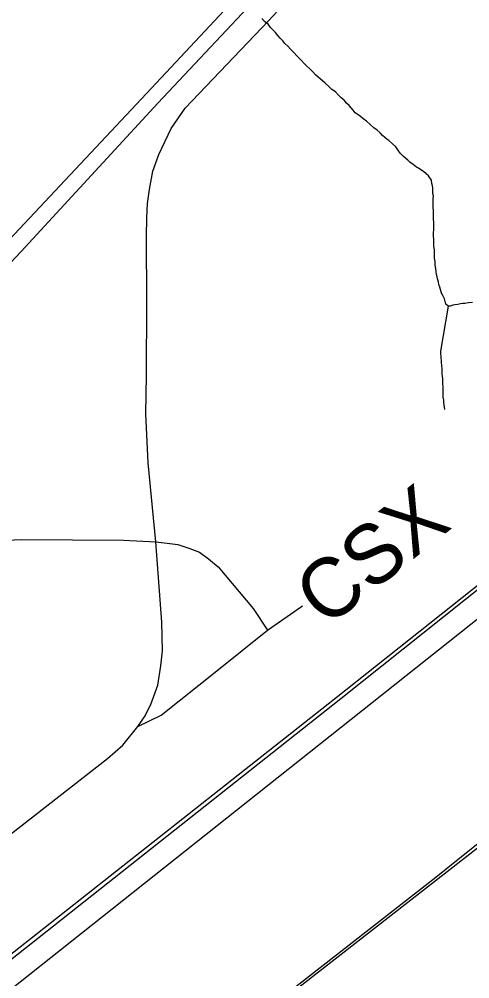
# Model space of a CAD drawing. Extents: x 0 to 34, y 0 to 22.
# Drawn here: x 7.775 to 8.206, y 15.889 to 16.806 of the extents above; entities that cross this region are included whole.
import ezdxf

# ---------------------------------------------------------------- set-up
doc = ezdxf.new("R2010")
doc.units = 0
for name, color, linetype in [('GM_X_City_Street', 7, 'Continuous'), ('GM_X_County_Road', 7, 'Continuous'), ('GM_X_Minor_River', 7, 'Continuous'), ('GM_X_Rail_Line', 7, 'Continuous'), ('GM_X_Rail_Line_Text', 7, 'Continuous'), ('GM_X_State_Route', 7, 'Continuous'), ('GM_X_US_Route', 7, 'Continuous')]:
    doc.layers.add(name, color=color, linetype=linetype)

msp = doc.modelspace()

# ---------------------------------------------------------------- linework, layer by layer
at = {"layer": 'GM_X_City_Street'}
for points in [[(7.65164, 16.30285), (7.77765, 16.30863), (7.87506, 16.30794), (7.90594, 16.30639), (7.91957, 16.30501), (7.92699, 16.3038), (7.93752, 16.30052), (7.94787, 16.29672), (7.95633, 16.29034), (7.96562, 16.28259), (7.99913, 16.24266), (8.01268, 16.22197)], [(7.9643, 16.18343), (8.01268, 16.22197), (8.04612, 16.24543)], [(7.88899, 16.12998), (7.91109, 16.14103), (7.9643, 16.18343)]]:
    msp.add_lwpolyline(points, dxfattribs=at)
at = {"layer": 'GM_X_County_Road'}
msp.add_lwpolyline([(7.73034, 15.99882), (7.85976, 16.09967), (7.87438, 16.11215), (7.88899, 16.12998), (7.89576, 16.14032), (7.90147, 16.15209), (7.90788, 16.16956), (7.91073, 16.1881), (7.91252, 16.20236), (7.9118, 16.22982), (7.90594, 16.30639), (7.89873, 16.38177), (7.89663, 16.4286), (7.89705, 16.46529), (7.89747, 16.53532), (7.89705, 16.59817), (7.89754, 16.61595), (7.89819, 16.62939), (7.89992, 16.64304), (7.90324, 16.66038), (7.90884, 16.67631), (7.92059, 16.70115), (7.9342, 16.72055), (8.01372, 16.80397), (8.59955, 17.43284)], dxfattribs=at)
at = {"layer": 'GM_X_Minor_River'}
for points in [[(8.17186, 16.6046), (8.17179, 16.60726), (8.17174, 16.60917), (8.17168, 16.61145), (8.17159, 16.61488), (8.17153, 16.61716), (8.17148, 16.61944), (8.17143, 16.62134), (8.17138, 16.62325), (8.17132, 16.62553), (8.17126, 16.62782), (8.1712, 16.6301), (8.17115, 16.632), (8.17111, 16.63391), (8.17141, 16.63696), (8.17097, 16.63923), (8.17092, 16.64114), (8.17083, 16.64456), (8.1704, 16.64646), (8.16996, 16.64873), (8.16951, 16.65177), (8.16673, 16.65588), (8.1644, 16.65773), (8.16206, 16.65995), (8.15935, 16.66179), (8.15702, 16.66325), (8.15509, 16.66435), (8.15197, 16.66693), (8.14887, 16.66914), (8.14692, 16.67099), (8.14498, 16.67247), (8.14263, 16.67469), (8.13951, 16.67766), (8.13753, 16.68066), (8.13555, 16.68365), (8.13242, 16.68662), (8.12892, 16.68958), (8.12698, 16.69105), (8.12503, 16.69252), (8.1227, 16.69437), (8.12035, 16.69698), (8.11762, 16.69957), (8.11451, 16.70178), (8.111, 16.70512), (8.10749, 16.70807), (8.104, 16.71065), (8.10167, 16.7125), (8.09933, 16.71434), (8.09662, 16.71618), (8.09465, 16.71879), (8.09269, 16.72103), (8.09072, 16.72326), (8.08838, 16.72549), (8.08603, 16.72809), (8.08331, 16.73031), (8.08057, 16.73291), (8.07782, 16.73626), (8.07434, 16.73846), (8.07121, 16.74143), (8.06809, 16.7444), (8.05874, 16.75254), (8.056, 16.75513), (8.05326, 16.75811), (8.05053, 16.76071), (8.04779, 16.7633), (8.04505, 16.76628), (8.04114, 16.77037), (8.038, 16.77372), (8.03487, 16.77707), (8.03214, 16.77966), (8.02941, 16.78226), (8.02743, 16.78487), (8.02508, 16.78748), (8.02273, 16.79009), (8.02038, 16.79269), (8.01803, 16.7953), (8.01568, 16.79752), (8.01331, 16.80089), (8.00982, 16.80347), (8.00746, 16.80608)], [(8.20868, 16.53508), (8.20489, 16.5346), (8.20147, 16.53414), (8.19957, 16.53409), (8.19729, 16.53365), (8.19464, 16.5332), (8.19198, 16.53275), (8.19009, 16.53232), (8.18744, 16.53149), (8.18554, 16.53145), (8.18321, 16.53329), (8.18193, 16.53859), (8.18033, 16.5416), (8.17913, 16.54385), (8.17828, 16.54726), (8.17746, 16.54952), (8.17663, 16.55216), (8.17618, 16.55482), (8.17535, 16.55746), (8.17492, 16.55936), (8.17448, 16.56163), (8.17403, 16.56429), (8.17357, 16.56732), (8.1731, 16.57073), (8.17302, 16.57416), (8.17256, 16.5772), (8.17245, 16.58138), (8.17235, 16.58519), (8.17188, 16.5886), (8.1718, 16.59203), (8.17171, 16.59546), (8.17163, 16.5985), (8.17155, 16.60154), (8.17186, 16.6046)], [(8.18554, 16.53145), (8.17825, 16.48861), (8.17833, 16.48556), (8.17838, 16.48366), (8.17843, 16.48176), (8.17886, 16.47986), (8.17892, 16.47758), (8.17898, 16.4753), (8.17946, 16.4715), (8.17952, 16.46884), (8.17958, 16.46655), (8.17963, 16.46465), (8.18007, 16.46237), (8.18014, 16.45971), (8.1802, 16.45743), (8.18026, 16.45476), (8.18034, 16.45172), (8.18039, 16.44982), (8.18047, 16.44677), (8.18053, 16.44449), (8.18098, 16.44183), (8.18103, 16.43955), (8.18153, 16.43499), (8.18207, 16.43282)]]:
    msp.add_lwpolyline(points, dxfattribs=at)
at = {"layer": 'GM_X_Rail_Line'}
for points in [[(6.62373, 15.15527), (6.67426, 15.16717), (6.73782, 15.18486), (6.81396, 15.21165), (6.89104, 15.24624), (6.95875, 15.28443), (7.00537, 15.31207), (7.05822, 15.35007), (7.28715, 15.53106), (7.65992, 15.8282), (8.07685, 16.15659), (8.5157, 16.50449), (8.89038, 16.79769), (8.90008, 16.80542)], [(6.62418, 15.15299), (6.67484, 15.16492), (6.73852, 15.18265), (6.81483, 15.20949), (6.89209, 15.24417), (6.95997, 15.28245), (7.00975, 15.31114), (7.06316, 15.34891), (7.28904, 15.52772), (7.66456, 15.82642), (8.08303, 16.1569), (8.51714, 16.50268), (8.89182, 16.79588), (8.90008, 16.80246)], [(6.62656, 14.98195), (6.63962, 14.98961), (6.65284, 14.99823), (6.6734, 15.01258), (6.68985, 15.02508), (7.03347, 15.29735), (7.12417, 15.36942), (7.23003, 15.45319), (7.3475, 15.54631), (7.42159, 15.60509), (7.51584, 15.67975), (7.62944, 15.76972), (7.73594, 15.85446), (8.09294, 16.1372), (8.38327, 16.36755), (8.71471, 16.63054), (8.90008, 16.7773)], [(8.90008, 16.27609), (8.28464, 16.05251), (8.2351, 16.03075), (7.62857, 15.55854), (7.35221, 15.32854), (6.98093, 15.0864), (6.94685, 15.07059), (6.85677, 15.01096), (6.78007, 14.94768), (6.74233, 14.92578), (6.48307, 14.82604), (6.41613, 14.80659), (6.31973, 14.75852), (6.2075, 14.68975), (6.18014, 14.67712), (6.14998, 14.67432), (6.11427, 14.67643), (6.10573, 14.62409), (6.06796, 14.54131), (6.04876, 14.50294)]]:
    msp.add_lwpolyline(points, dxfattribs=at)
at = {"layer": 'GM_X_State_Route'}
for points in [[(7.01703, 15.87077), (7.0512, 15.88923), (7.08197, 15.90699), (7.11642, 15.92891), (7.14444, 15.94838), (7.16808, 15.96709), (7.18754, 15.98339), (7.20781, 16.00092), (7.2333, 16.02476), (7.30059, 16.09567), (7.34997, 16.14757), (7.40786, 16.21064), (7.54366, 16.35792), (7.58575, 16.40231), (7.66613, 16.48747), (7.76583, 16.59473), (7.89725, 16.73462), (8.09201, 16.94317)], [(7.54128, 16.33413), (7.5433, 16.33632), (7.58701, 16.38216), (7.67698, 16.47746), (7.77734, 16.58372), (7.90806, 16.72532), (8.04911, 16.87572)]]:
    msp.add_lwpolyline(points, dxfattribs=at)
at = {"layer": 'GM_X_US_Route'}
for points in [[(8.18371, 15.99435), (8.2126, 16.01746), (8.23166, 16.02866), (8.24525, 16.03546), (8.25949, 16.04323), (8.53263, 16.14355), (8.5485, 16.14937)], [(7.7191, 15.62562), (7.77826, 15.67364), (7.85269, 15.73384), (7.95593, 15.81507), (8.04266, 15.884), (8.17357, 15.98622), (8.18371, 15.99435)]]:
    msp.add_lwpolyline(points, dxfattribs=at)

# ---------------------------------------------------------------- texts
at = {"layer": 'GM_X_Rail_Line_Text'}
msp.add_text('CSX', height=0.056629, rotation=38.61909, dxfattribs=at).set_placement((8.06878, 16.2232))

doc.saveas('drawing.dxf')
